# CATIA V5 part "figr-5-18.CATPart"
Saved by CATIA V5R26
Part number: Part1
Bounding box of the stored display mesh (mm): x -50 to 50, y -70 to 70, z -20 to 40
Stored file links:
  D:\_Deepak\CATIA\CATIA V5-6R2016_Deepak\Resources\Part files\Partfiles\c05_catia_v5_6r2016_prt\figr-5-18.CATPart
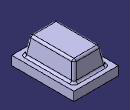
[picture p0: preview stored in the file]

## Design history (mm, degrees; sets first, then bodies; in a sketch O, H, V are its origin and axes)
Body1 (main body)
  Sketch1 on xy-plane, origin (0, 0, 0), H (1, 0, 0), V (0, 1, 0)
    line L1 (50, 70) -> (50, -70)
    line L2 (50, -70) -> (-50, -70)
    line L3 (-50, -70) -> (-50, 70)
    line L4 (-50, 70) -> (50, 70)
    length L2 = 100
    length L1 = 140
    vertical: L1 V, L3 V
    horizontal: L2 H, L4 H
    equidistance: L1 L3 O, L2 L4 O
  Pad1: profile Sketch1, direction (0, 0, -1), length 20
  Sketch2 on face of Pad1, origin (0, 0, 0), H (1, 0, 0), V (0, 1, 0)
    line L1 (30, 50) -> (30, -50)
    line L2 (30, -50) -> (-30, -50)
    line L3 (-30, -50) -> (-30, 50)
    line L4 (-30, 50) -> (30, 50)
    length L2 = 60
    length L1 = 100
    vertical: L1 V, L3 V
    horizontal: L2 H, L4 H
    equidistance: L1 L3 O, L2 L4 O
  Pad2: profile Sketch2, direction (0, 0, 1), length 40, opposite side up to face of Pad1
  Draft1: Angle 9, Neutral face of Pad2, PullDir face of Pad2, SupportToDraft (face of Pad2; face of Pad2; face of Pad2; face of Pad2)
  Fillet1: radius 5, on edge [face of Pad2 | face of Pad2] (x4)
  Fillet2: radius 5, on edge [face of Pad2 | face of Pad2] (x4)
  Fillet3: radius 5, on edge [face of Pad2 | face of Pad1] (x4)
